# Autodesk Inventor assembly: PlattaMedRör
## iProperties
Company: Autodesk EMEA
Shininess: 64.0
Length Units: 11269
Angle Units: 11279
Time Units: 11290
Mass Units: 11283
Length Display Precision: 3
Angle Display Precision: 2
Compacted: True
Created: 2002-08
Part Number: PlattaMedRör
Document SubType Name: Assembly
Designer: Franz Kaltseis
Density: 0.0
Volumn: 0.0
Area: 0.0
PropertySet Name: Model Information
Control State: 0
Master: False
Checked Out: False
Author: Franz Kaltseis
